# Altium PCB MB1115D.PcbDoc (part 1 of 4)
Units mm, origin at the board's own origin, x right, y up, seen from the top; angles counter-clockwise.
Board outline 66 x 97 mm, 2 copper layers (TOP, Bottom), stack 1.535 mm thick; 198 components, 186 nets, 760 pads, 493 vias.
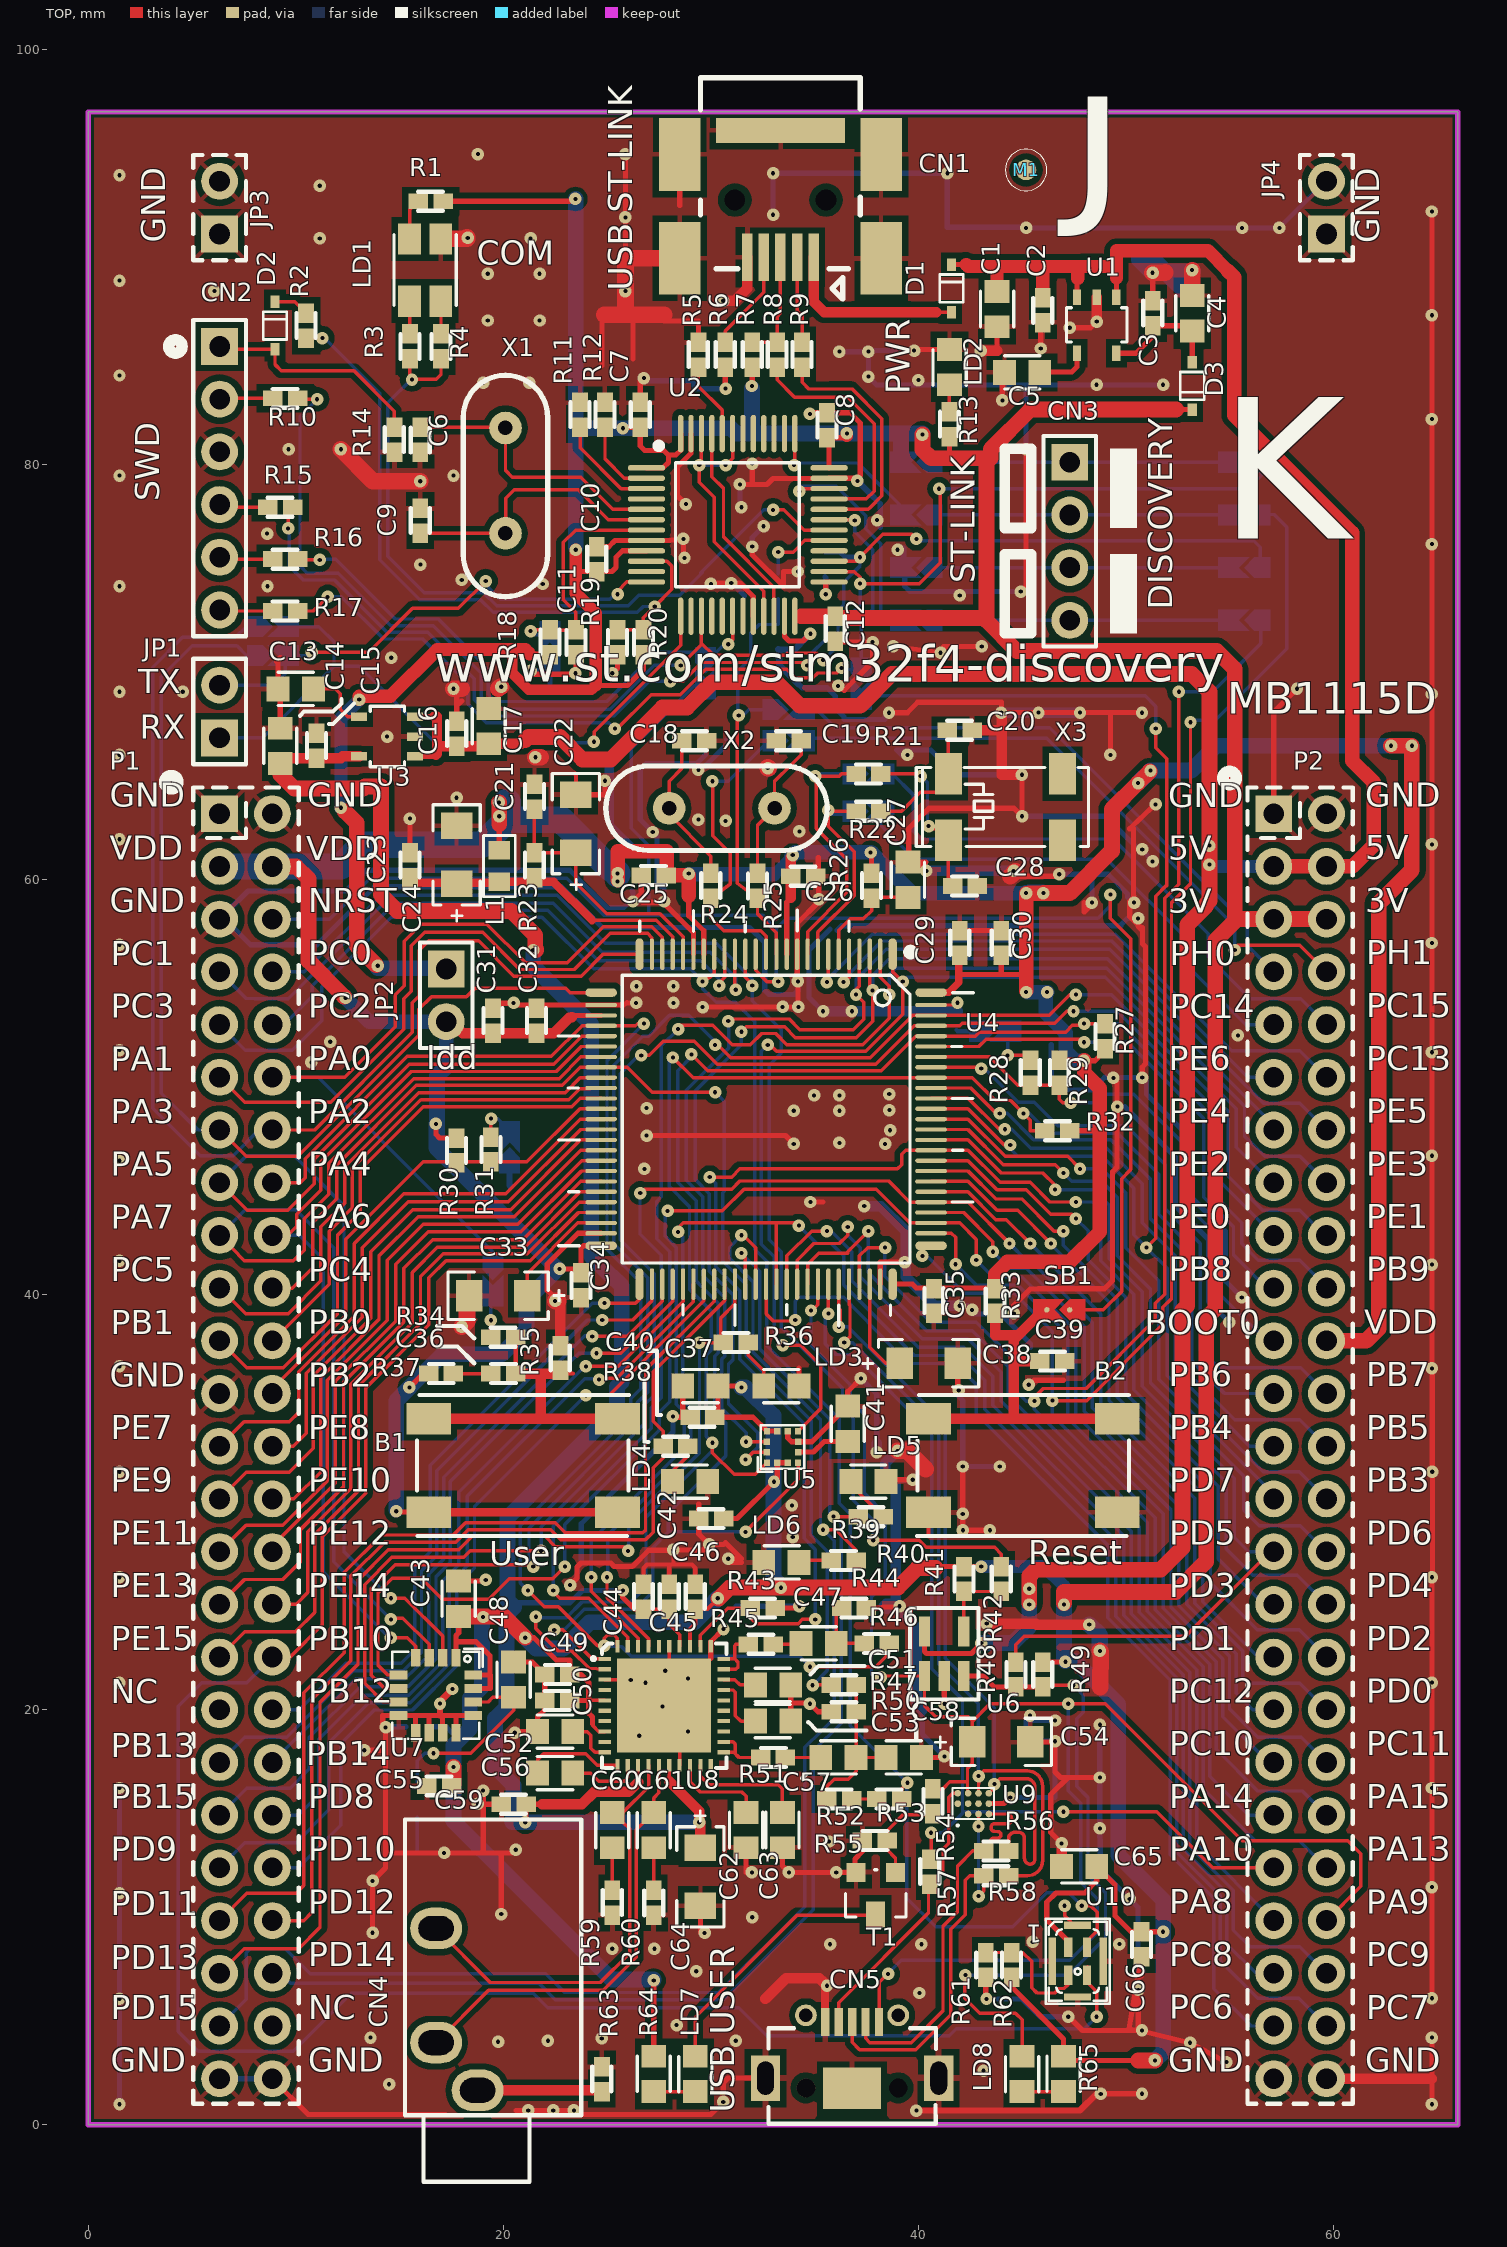
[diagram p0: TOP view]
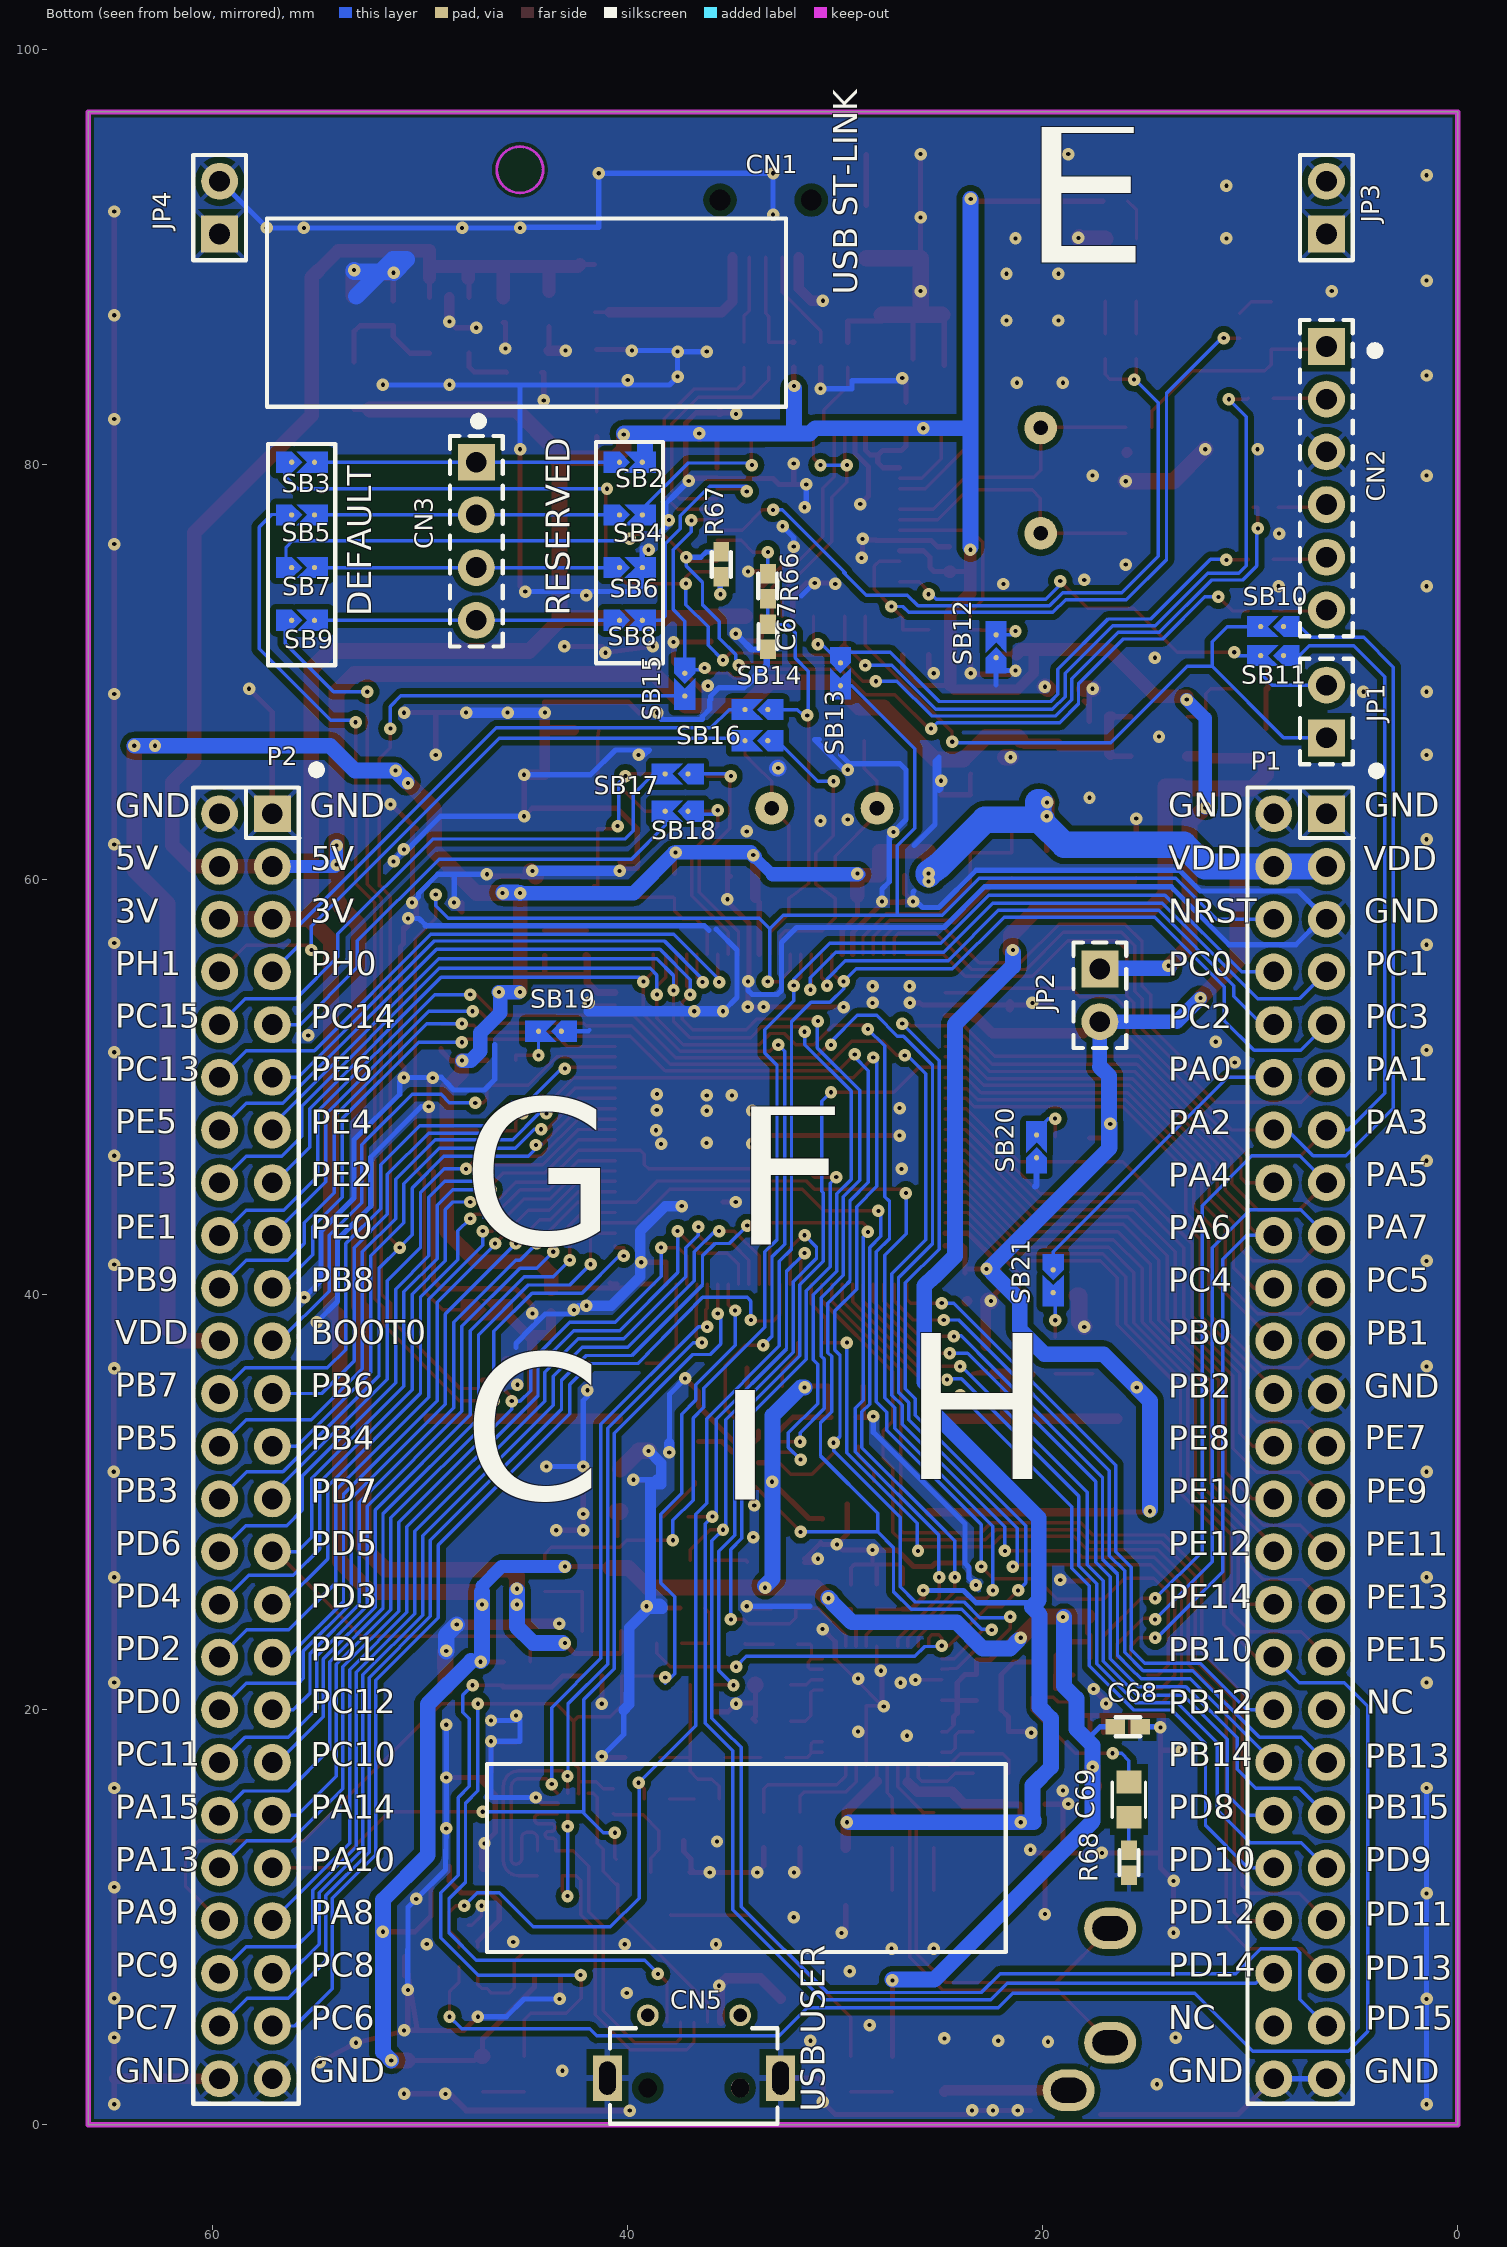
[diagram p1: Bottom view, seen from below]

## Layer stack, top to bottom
Top Mask: solder mask 0.018, Solder Resist, Dk 3.5
TOP: signal copper 0.035
Dielectric 1: dielectric 1.465, FR-4, Dk 4.8
Bottom: signal copper 0.035
Bottom Solder: solder mask 0.018, Solder Resist, Dk 3.5

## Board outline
0,0 66,0 66,97 0,97

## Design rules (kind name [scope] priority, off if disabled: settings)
Clearance Clearance_SB [(ObjectKind = 'Region')  and IsComponentPrimitive vs InNet('GND')     and InPolygon] p1: gap=0.28 ignorepadtopadclearanceinfootprint=TRUE
Clearance Clearance_JP2_SMD [HasFootprint('JP2_SMD (Primary)') and IsComponentPrimitive and IsRegion or IsTrack or InPolygon or IsVia vs HasFootprint('JP2_SMD (Primary)') and IsComponentPrimitive and IsRegion] p2: gap=0.1 ignorepadtopadclearanceinfootprint=FALSE
Clearance InPolygon_Template_1 [InNamedPolygon('Template_1') vs InNet('GND')] p3: gap=0.3 ignorepadtopadclearanceinfootprint=FALSE
Clearance InPolygon_Template_3 [InNamedPolygon('Template_3') vs InNet('GND')] p4: gap=0.3 ignorepadtopadclearanceinfootprint=FALSE
Clearance CopperToBoard [InPolygon vs IsKeepOut] p5: gap=0.15 ignorepadtopadclearanceinfootprint=FALSE
Clearance PadToCopper [IsPad vs InPolygon] p6: gap=0.3 ignorepadtopadclearanceinfootprint=FALSE
Clearance [All] p7: gap=0.15 ignorepadtopadclearanceinfootprint=FALSE except(0.28: Arc-Fill Arc-Poly Arc-Region Track-Fill Track-Poly Track-Region SMDPad-Fill SMDPad-Poly SMDPad-Region THPad-Fill THPad-Poly THPad-Region Via-Fill Via-Poly Via-Region)
ComponentClearance [All   and not HasFootprint('VIA') vs All and not HasFootprint('VIA')] p1: gap=0.07 collisioncheckmode=3 verticalgap=0.03 showdistances=FALSE
PolygonConnect PolygonConnect_HLGA [HasFootprint('HLGA-4.72-3.76-6LD (Primary)')] p1: connectstyle=Relief reliefconductorwidth=0.2 reliefentries=4 polygonreliefangle="45 Angle" airgapwidth=0.3
PolygonConnect PolygonConnect_CN5 [(ObjectKind = 'Pad') And ((Name = 'CN5-7') or  (Name = 'CN5-8'))] p2: connectstyle=Relief reliefconductorwidth=0.3 reliefentries=4 polygonreliefangle="90 Angle" airgapwidth=0.3
PolygonConnect PolygonConnect_Via [HasFootprint('VIA')] p3: connectstyle=Direct reliefconductorwidth=0.254 reliefentries=4 polygonreliefangle="90 Angle" airgapwidth=0.254
PolygonConnect [All] p4: thpad.connectstyle=Relief thpad.reliefconductorwidth=0.21 thpad.reliefentries=4 thpad.polygonreliefangle="45 Angle" thpad.airgapwidth=0.3 smdpad.connectstyle=Relief smdpad.reliefconductorwidth=0.23 smdpad.reliefentries=4 smdpad.polygonreliefangle="90 Angle" smdpad.airgapwidth=0.3 via.connectstyle=Direct via.reliefconductorwidth=0.2 via.reliefentries=4 via.polygonreliefangle="45 Angle" via.airgapwidth=0.2
RoutingVias [All] p1: holewidth=0.2 width=0.6 viastyle="Through Hole" minholewidth=0.2 minwidth=0.6 maxholewidth=0.2 maxwidth=0.6
SolderMaskExpansion [All] p1: expansion=0.05
Width [All] p1: maxlimit=1.27 minlimit=0.165 preferedwidth=0.175
29 further rules are at their usual default settings.

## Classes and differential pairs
component class U_MB1115_TOP: P1 P2
component class U_Audio: C44 C45 C46 C47 C49 C50 C51 C52 C53 C56 C57 C58 C59 C60 C61 C62 C63 C64 C65 C66 CN4 R43 R44 R45 R46 R47 R50 R51 R52 R53 R59 R60 R61 R62 R63 U8 U10
component class "U_IO Peripherals": B1 B2 C36 C37 C39 C40 C41 C42 C43 C48 C55 C68 C69 LD3 LD4 LD5 LD6 R33 R34 R35 R36 R37 R38 R39 R40 R68 SB1 SB21 U5 U7
component class U_ST_LINK: C1 C2 C3 C4 C5 C6 C7 C8 C9 C10 C11 C12 C13 C14 C15 C16 C17 C67 CN1 CN2 CN3 D1 D2 D3 JP1 JP2 JP3 JP4 LD1 LD2 R1 R2 R3 R4 R5 R6 R7 R8 R9 R10 R11 R12 R13 R14 R15 R16 R17 R18 R19 R20 R66 R67 SB2 SB3 SB4 SB5 SB6 SB7 SB8 SB9 SB10 SB11 SB12 SB13 SB15 U1 U2 U3 X1
component class U_STM32Fx: C18 C19 C20 C21 C22 C23 C24 C25 C26 C27 C28 C29 C30 C31 C32 C33 C34 C35 C38 L1 R21 R22 R23 R24 R25 R26 R27 R28 R29 R30 R31 R32 SB14 SB16 SB17 SB18 SB19 SB20 U4 X2 X3
component class U_USB_OTG_FS: C54 CN5 LD7 LD8 R41 R42 R48 R49 R54 R55 R56 R57 R58 R64 R65 T1 U6 U9

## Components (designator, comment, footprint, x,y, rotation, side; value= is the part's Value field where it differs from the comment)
B1 "SW-PUSH-CMS_BLUE" "BP1CMS (Primary)" 20.96,31.773 r90 top
B2 "SW-PUSH-CMS_BLACK" "BP1CMS (Primary)" 45.04,31.773 r270 top
C1 "1uF" "0603C (Primary)" 43.8,87.5 r90 top
C2 "100nF" "0402C (Primary)" 46,87.45 r180 top
C3 "100nF" "0402C (Primary)" 51.3,87.3 r0 top
C4 "1uF" "0603C (Primary)" 53.2,87.3 r90 top
C5 "10nF" "0603C (Primary)" 45,84.45 r0 top
C6 "20pF" "0402C (Primary)" 16,81.2 r180 top
C7 "100nF" "0402C (Primary)" 26.6,82.4 r0 top
C8 "100nF" "0402C (Primary)" 35.6,81.9 r0 top
C9 "20pF" "0402C (Primary)" 16,77.3 r0 top
C10 "100nF" "0402C (Primary)" 24.5,75.45 r0 top
C11 "100nF" "0402C (Primary)" 23.5,71.45 r180 top
C12 "100nF" "0402C (Primary)" 36,72.1 r0 top
C13 "10nF" "0603C (Primary)" 10,69.2 r0 top
C14 "1uF" "0603C (Primary)" 9.25,66.45 r90 top
C15 "100nF" "0402C (Primary)" 11,66.45 r0 top
C16 "100nF" "0402C (Primary)" 17.76,67.028 r0 top
C17 "1uF" "0603C (Primary)" 19.3,67.4 r270 top
C18 "20pF" "0402C (Primary)" 29.2,66.7 r270 top
C19 "20pF" "0402C (Primary)" 33.75,66.7 r90 top
C20 "6.8pF" "0402C (Primary)" 42,67.2 r90 top
C21 "100nF" "0402C (Primary)" 21.5,64 r0 top
C22 "1uF" "TAN-A (Primary)" 23.5,62.7 r270 top
C23 "100nF" "0402C (Primary)" 15.5,60.7 r0 top
C24 "1uF" "TAN-A (Primary)" 17.75,61.2 r270 top
C25 "100nF" "0402C (Primary)" 27.25,60.2 r90 top
C26 "100nF" "0402C (Primary)" 34.461,60.17 r90 top
C27 "1uF" "0603C (Primary)" 39.5,60 r90 top
C28 "6.8pF" "0402C (Primary)" 42.25,59.7 r90 top
C29 "100nF" "0402C (Primary)" 42,56.95 r0 top
C30 "100nF" "0402C (Primary)" 44,56.95 r0 top
C31 "100nF" "0402C (Primary)" 19.5,53.2 r0 top
C32 "100nF" "0402C (Primary)" 21.6,53.2 r0 top
C33 "2.2uF" "TAN-A (Primary)" 19.75,39.95 r0 top
C34 "100nF" "0402C (Primary)" 23.75,40.45 r180 top
C35 "100nF" "0402C (Primary)" 40.75,39.7 r0 top
C36 "[NA]" "0402C (Primary)" 20,36.2 r270 top
C37 "10uF" "0603C (Primary)" 29.5,35.6 r0 top
C38 "2.2uF" "TAN-A (Primary)" 40.5,36.7 r180 top
C39 "100nF" "0402C (Primary)" 46.45,36.8 r270 top
C40 "100nF" "0402C (Primary)" 29.6,34.1 r90 top
C41 "220nF" "0603C (Primary)" 36.598,33.782 r270 top
C42 "100nF" "0402C (Primary)" 30.02,29.21 r90 top
C43 "10uF" "0603C (Primary)" 17.85,25.35 r270 top
C44 "100nF" "0402C (Primary)" 26.75,25.45 r0 top
C45 "100nF" "0402C (Primary)" 28,25.45 r0 top
C46 "100nF" "0402C (Primary)" 29.25,25.45 r0 top
C47 "1uF" "0603C (Primary)" 35.2,23.2 r0 top
C48 "10nF" "0603C (Primary)" 20.5,21.45 r270 top
C49 "100nF" "0402C (Primary)" 22.6,21.7 r270 top
C50 "100nF" "0402C (Primary)" 22.6,20.45 r90 top
C51 "150pF" "0603C (Primary)" 33,21.2 r180 top
C52 "1uF" "0603C (Primary)" 22.5,18.95 r180 top
C53 "150pF" "0603C (Primary)" 33,19.45 r180 top
C54 "4.7uF" "TAN-A (Primary)" 44,18.45 r180 top
C55 "100nF" "0402C (Primary)" 16.916,16.332 r90 top
C56 "1uF" "0603C (Primary)" 22.5,16.95 r180 top
C57 "1uF" "0603C (Primary)" 36.15,17.7 r0 top
C58 "10nF" "0603C (Primary)" 39.3,17.7 r0 top
C59 "100nF" "0402C (Primary)" 20.5,15.45 r90 top
C60 "22nF" "0603C (Primary)" 25.25,14.2 r270 top
C61 "22nF" "0603C (Primary)" 27.25,14.2 r270 top
C62 "1uF" "0603C (Primary)" 31.7,14.2 r90 top
C63 "1uF" "0603C (Primary)" 33.45,14.2 r90 top
C64 "1uF" "TAN-A (Primary)" 29.5,11.95 r90 top
C65 "1uF" "0603C (Primary)" 47.75,12.45 r0 top
C66 "100nF" "0402C (Primary)" 50.75,8.7 r180 top
C67 "20pF" "0402C (Primary)" 33.25,71.7 r180 bottom
C68 "100nF" "0402C (Primary)" 15.91,19.177 r270 bottom
C69 "Capacitor" "0603C (Primary)" 15.85,15.672 r270 bottom value=470nF
CN1 "USB-MINI-typeB" "USB-MINI-B-SMD (Primary)" 33.359,92.751 r0 top
CN2 "Header 6" "HDR1X6 (PRIMARY)" 6.33,85.7 r270 top
CN3 "Header 4" "HEADER 4 (PRIMARY)" 47.299,80.121 r270 top
CN4 "ST-225-02" "JACK-ST-225 (Primary)" 17.76,5.56 r90 top
CN5 "USB-MICRO-AB" "USB-MICRO-AB (PRIMARY)" 36.81,4.95 r90 top
D1 "BAT60JFILM" "SOD323/A (Primary)" 41.6,88.5 r270 top
D2 "BAT60JFILM" "SOD323/A (Primary)" 9,86.7 r270 top
D3 "BAT60JFILM" "SOD323/A (Primary)" 53.2,83.8 r90 top
JP1 "JP2" "SIP2/2.54 (PRIMARY)" 6.33,66.837 r90 top
JP2 "" "SIP2/2.54 (PRIMARY)" 17.25,55.7 r270 top
JP3 "" "SIP2/2.54 (PRIMARY)" 6.33,91.12 r90 bottom
JP4 "" "SIP2/2.54 (PRIMARY)" 59.67,91.12 r90 bottom
L1 "Ferrite" "0603L (Primary)" 19.807,60.66 r270 top value=100uH
LD1 "LD_BICOLOR_CMS" "HSMF-A201 (Primary)" 16.236,89.38 r270 top
LD2 "LED, red" "0603D (Primary)" 41.5,84.7 r90 top
LD3 "LED, orange" "0603D (Primary)" 33.4,35.6 r0 top
LD4 "LED, green" "0603D (Primary)" 29,31 r0 top
LD5 "LED, red" "0603D (Primary)" 37.6,31 r0 top
LD6 "LED, blue" "0603D (Primary)" 33.4,27.1 r180 top
LD7 "LED, green" "0603D (Primary)" 29.25,2.45 r90 top
LD8 "LED, red" "0603D (Primary)" 45,2.45 r90 top
M1 "Comment" "SMDPAD-T (PRIMARY)" 45.192,94.206 r0 top
P1 "Header 25X2" "HDR2X25 (PRIMARY)" 7.6,32.7 r270 top
P2 "Header 25X2" "HDR2X25 (PRIMARY)" 58.4,32.7 r270 top
R1 "0" "0402R (Primary)" 16.5,92.7 r90 top
R2 "[NA]" "0402R (Primary)" 10.5,86.7 r0 top
R3 "100" "0402R (Primary)" 15.5,85.7 r180 top
R4 "100" "0402R (Primary)" 17,85.7 r180 top
R5 "100K" "0402R (Primary)" 29.4,85.3 r0 top
R6 "100K" "0402R (Primary)" 30.7,85.3 r0 top
R7 "1K5" "0402R (Primary)" 32,85.3 r0 top
R8 "0" "0402R (Primary)" 33.2,85.3 r0 top
R9 "0" "0402R (Primary)" 34.4,85.3 r0 top
R10 "22" "0402R (Primary)" 9.5,83.2 r90 top
R11 "[NA]" "0402R (Primary)" 23.7,82.4 r0 top
R12 "10K" "0402R (Primary)" 24.9,82.4 r0 top
R13 "1K" "0402R (Primary)" 41.5,81.95 r0 top
R14 "10K" "0402R (Primary)" 14.75,81.2 r0 top
R15 "22" "0402R (Primary)" 9.25,77.95 r90 top
R16 "22" "0402R (Primary)" 9.5,75.45 r90 top
R17 "22" "0402R (Primary)" 9.5,72.95 r90 top
R18 "100K" "0402R (Primary)" 22.25,71.45 r0 top
R19 "4K7" "0402R (Primary)" 25.5,71.45 r180 top
R20 "4K7" "0402R (Primary)" 26.75,71.45 r180 top
R21 "0" "0402R (Primary)" 37.6,65.1 r90 top
R22 "0" "0402R (Primary)" 37.6,63.3 r90 top
R23 "47" "0402R (Primary)" 21.5,60.7 r0 top value=1K
R24 "220" "0402R (Primary)" 30,59.7 r0 top
R25 "0" "0402R (Primary)" 32.25,59.7 r180 top
R26 "0" "0402R (Primary)" 37.75,59.7 r0 top
R27 "4.7K" "0402R (Primary)" 49,52.45 r180 top value=10K
R28 "510" "0402R (Primary)" 45.4,50.7 r0 top
R29 "[NA]" "0402R (Primary)" 46.8,50.7 r0 top
R30 "10K" "0402R (Primary)" 17.75,46.95 r0 top
R31 "510" "0402R (Primary)" 19.4,47 r180 top
R32 "4.7K" "0402R (Primary)" 46.7,47.9 r270 top value=10K
R33 "[NA]" "0402R (Primary)" 43.7,39.7 r180 top
R34 "330" "0402R (Primary)" 20,37.95 r90 top
R35 "220K" "0402R (Primary)" 22.75,36.95 r0 top value=10K
R36 "1K" "0402R (Primary)" 31.2,37.7 r270 top
R37 "100" "0402R (Primary)" 17,36.2 r270 top value=330
R38 "330" "0402R (Primary)" 28.3,32.7 r270 top value=1K
R39 "1K" "0402R (Primary)" 37.7,29.3 r270 top
R40 "510" "0402R (Primary)" 36.4,27.2 r90 top value=1K
R41 "10K" "0402R (Primary)" 42.2,26.3 r0 top value=1K
R42 "0" "0402R (Primary)" 44,26.3 r0 top
R43 "10K" "0402R (Primary)" 32.5,24.9 r90 top value=1K
R44 "100K" "0402R (Primary)" 36.9,24.9 r90 top value=1K
R45 "100" "0402R (Primary)" 32.4,23.15 r270 top value=1K
R46 "[NA]" "0402R (Primary)" 38,23.2 r90 top
R47 "[NA]" "0402R (Primary)" 36.4,21.2 r270 top
R48 "0" "0402R (Primary)" 44.7,21.7 r180 top
R49 "47K" "0402R (Primary)" 46,21.7 r0 top value=1K
R50 "100K" "0402R (Primary)" 36.4,19.9 r270 top value=1K
R51 "100" "0402R (Primary)" 33,17.7 r270 top value=1K
R52 "1.2K" "0402R (Primary)" 36.2,15.7 r90 top
R53 "0" "0402R (Primary)" 38.6,15.7 r90 top
R54 "47K" "0402R (Primary)" 40.7,15.6 r180 top value=1K
R55 "[NA]" "0402R (Primary)" 37.9,13.7 r270 top
R56 "22" "0402R (Primary)" 43.75,13.2 r90 top value=1K
R57 "0" "0402R (Primary)" 40.55,12.2 r0 top
R58 "22" "0402R (Primary)" 43.75,12 r90 top value=1K
R59 "51" "0402R (Primary)" 25.25,10.7 r0 top value=1K
R60 "51" "0402R (Primary)" 27.25,10.7 r180 top value=1K
R61 "0" "0402R (Primary)" 43.25,7.7 r180 top
R62 "[NA]" "0402R (Primary)" 44.5,7.7 r0 top
R63 "0" "0402R (Primary)" 24.75,2.2 r0 top
R64 "330" "0603R (Primary)" 27.25,2.45 r90 top value=1K
R65 "620" "0603R (Primary)" 47,2.45 r90 top value=1K
R66 "100" "0402R (Primary)" 33.25,74.15 r180 bottom
R67 "100" "0402R (Primary)" 35.5,75.2 r0 bottom
R68 "10K" "0402R (Primary)" 15.85,12.624 r180 bottom
SB1 "Circuit Breaker" "JP2_SMD (PRIMARY)" 46.793,39.271 r180 top
SB2 "Circuit Breaker" "JP2_SMD (PRIMARY)" 39.899,80.121 r180 bottom
SB3 "Circuit Breaker" "JP2_SMD (PRIMARY)" 55.699,80.121 r180 bottom
SB4 "Circuit Breaker" "JP2_SMD (PRIMARY)" 39.899,77.581 r180 bottom
SB5 "Circuit Breaker" "JP2_SMD (PRIMARY)" 55.699,77.581 r180 bottom
SB6 "Circuit Breaker" "JP2_SMD (PRIMARY)" 39.899,75.041 r180 bottom
SB7 "Circuit Breaker" "JP2_SMD (PRIMARY)" 55.699,75.041 r180 bottom
SB8 "Circuit Breaker" "JP2_SMD (PRIMARY)" 39.899,72.501 r180 bottom
SB9 "Circuit Breaker" "JP2_SMD (PRIMARY)" 55.699,72.501 r180 bottom
SB10 "Circuit Breaker" "JP2_SMD (PRIMARY)" 8.9,72.2 r0 bottom
SB11 "Circuit Breaker" "JP2_SMD (PRIMARY)" 8.9,70.8 r0 bottom
SB12 "Circuit Breaker" "JP2_SMD (PRIMARY)" 22.25,71.2 r90 bottom
SB13 "Circuit Breaker" "JP2_SMD (PRIMARY)" 29.75,69.95 r270 bottom
SB14 "Circuit Breaker" "JP2_SMD (PRIMARY)" 33.75,68.2 r0 bottom
SB15 "Circuit Breaker" "JP2_SMD (PRIMARY)" 37.25,69.45 r270 bottom
SB16 "Circuit Breaker" "JP2_SMD (PRIMARY)" 33.75,66.7 r0 bottom
SB17 "Circuit Breaker" "JP2_SMD (PRIMARY)" 37.6,65.1 r0 bottom
SB18 "Circuit Breaker" "JP2_SMD (PRIMARY)" 37.6,63.3 r0 bottom
SB19 "Circuit Breaker" "JP2_SMD (PRIMARY)" 43.7,52.7 r0 bottom
SB20 "Circuit Breaker" "JP2_SMD (PRIMARY)" 20.3,47.1 r90 bottom
SB21 "Circuit Breaker" "JP2_SMD (PRIMARY)" 19.5,40.7 r270 bottom
T1 "9013-SOT23" "SOT23 (Primary)" 37.95,11.15 r90 top
U1 "LD3985M33R" "SOT-23-5L (Primary)" 48.599,86.721 r270 top
U2 "STM32F103C8T6" "LQFP48 (Primary)" 31.3,77.1 r0 top
U3 "LD3985M25R" "SOT-23-5L (Primary)" 14.4,66.9 r180 top
U4 "STM32F411VET6U" "TQFP100_14X14 (PRIMARY)" 32.664,48.462 r180 top
U5 "LSM303AGR" ICC_LGA12_2X2_P050 33.456,32.664 r90 top
U6 "STMPS2141STR" "SOT23-5L (PRIMARY)" 41.25,22.7 r0 top
U7 "I3G4250D" ICC_LGA16_4X4_P065_H1P1 16.75,20.7 r270 top
U8 "CS43L22" "QFN40_6X6 (PRIMARY)" 27.75,20.2 r0 top
U9 "EMIF02-USB03F2" "FLIP CHIP (PRIMARY)" 42.9,15.475 r90 top
U10 "IMP34DT05TR" MIC_HCLGA_3X4X1_4LD 47.683,7.886 r180 top
X1 "8MHz" "XTAL1 (Primary)" 20.1,76.7 r90 top
X2 "8MHz" "XTAL1 (Primary)" 28,63.45 r0 top
X3 "XTAL_32K_20PPM" "MC306-CRYSTAL (Primary)" 44.2,63.5 r0 top

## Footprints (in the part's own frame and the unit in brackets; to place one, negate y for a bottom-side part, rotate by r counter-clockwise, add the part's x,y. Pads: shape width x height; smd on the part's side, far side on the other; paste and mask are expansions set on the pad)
"0402C (Primary)" [mil]
  rect 30x37 smd paste+0 mask+1.97: 1(0,23.62) 2(0,-23.62)
  silkscreen extent -18,-23 18,24
"0402R (Primary)" [mil]
  rect 30x37 smd paste+0 mask+1.97: 1(0,23.62) 2(0,-23.62)
  silkscreen extent -18,-23 18,24
"0603C (Primary)" [mm]
  rect 1.1x1.2 smd paste+0 mask+0.05: 1(-0.85,0) 2(0.85,0)
  silkscreen extent -0.85,-0.8 0.86,0.8
"0603D (Primary)" [mm]
  rect 1.1x1.2 smd paste+0 mask+0.05: 1(-0.85,0) 2(0.85,0)
  silkscreen extent -0.86,-0.8 0.84,0.8
"0603L (Primary)" [mil]
  rect 35x40 smd paste+0 mask+1.97: 1(-30,0) 2(30,0)
  silkscreen extent -58,-30 58,30
"0603R (Primary)" [mm]
  rect 1.1x1.2 smd paste+0 mask+0.05: 1(-0.85,0) 2(0.85,0)
  silkscreen extent -0.85,-0.8 0.86,0.8
"BP1CMS (Primary)" [mm]
  rect 1.52x2.16 smd paste+0 mask+0.05: 1(-2.25,-4.55) 2(2.25,-4.55) 3(2.25,4.55) 4(-2.25,4.55)
  silkscreen extent -3.4,-5.1 3.4,5.12
"FLIP CHIP (PRIMARY)" [mm]
  round 0.32 smd paste-0.05 mask+0.05: A2(0,1) A3(0.5,1) B1(-0.5,0.5) B2(0,0.5) B3(0.5,0.5) C1(-0.5,0) C2(0,0) C3(0.5,0) D1(-0.5,-0.5) D2(0,-0.5) D3(0.5,-0.5)
  silkscreen extent -1.1,-0.75 0.75,1.25
"HDR1X6 (PRIMARY)" [mil]
  rect 70x70 / inner round 60 / far side rect 70x70 hole 39.37 paste+0 mask+1.97: 1(0,0)
  round 70 / inner round 60 / far side round 70 hole 39.37 paste+0 mask+1.97: 2(100,0) 3(200,0) 4(300,0) 5(400,0) 6(500,0)
  silkscreen extent -50,-50 550,50
"HDR2X25 (PRIMARY)" [mil]
  rect 70x70 / inner round 60 / far side rect 70x70 hole 39.37 paste+0 mask+1.97: 1(-1200,-50)
  round 70 / inner round 60 / far side round 70 hole 39.37 paste+0 mask+1.97: 2(-1200,50) 3(-1100,-50) 4(-1100,50) 5(-1000,-50) 6(-1000,50) 7(-900,-50) 8(-900,50) 9(-800,-50) 10(-800,50) 11(-700,-50) 12(-700,50) 13(-600,-50) 14(-600,50) 15(-500,-50) 16(-500,50) 17(-400,-50) 18(-400,50) 19(-300,-50) 20(-300,50) 21(-200,-50) 22(-200,50) 23(-100,-50) 24(-100,50) 25(0,-50) 26(0,50) 27(100,-50) 28(100,50) 29(200,-50) 30(200,50) 31(300,-50) 32(300,50) 33(400,-50) 34(400,50) 35(500,-50) 36(500,50) 37(600,-50) 38(600,50) 39(700,-50) 40(700,50) 41(800,-50) 42(800,50) 43(900,-50) 44(900,50) 45(1000,-50) 46(1000,50) 47(1100,-50) 48(1100,50) 49(1200,-50) 50(1200,50)
  silkscreen extent -1250,-100 1248,100
"HEADER 4 (PRIMARY)" [mil]
  rect 70x70 / inner round 60 / far side rect 70x70 hole 39.37 paste+0 mask+1.97: 1(0,0)
  round 70 / inner round 60 / far side round 70 hole 39.37 paste+0 mask+1.97: 2(100,0) 3(200,0) 4(300,0)
  silkscreen extent -50,-50 350,50
"HSMF-A201 (Primary)" [mm]
  rect 1.5x1.1 smd paste+0 mask+0.05: 1(-1.5,0.75) 2(1.5,0.75) 3(1.5,-0.75) 4(-1.5,-0.75)
  silkscreen extent -1.7,-1.5 1.7,1.5
ICC_LGA12_2X2_P050 [mm] "MCD-00709"
  rect 0.325x0.3 smd mask+0.05: 1(-0.763,0.75) 2(-0.763,0.25) 3(-0.763,-0.25) 4(-0.763,-0.75) 7(0.763,-0.75) 8(0.763,-0.25) 9(0.763,0.25) 10(0.763,0.75)
  rect 0.3x0.325 smd mask+0.05: 5(-0.25,-0.762) 6(0.25,-0.762) 11(0.25,0.763) 12(-0.25,0.763)
  silkscreen extent -1.2,-1.05 1.05,1.2, body extent -1.05,-1.05 1.05,1.05, height 1.01
ICC_LGA16_4X4_P065_H1P1 [mm] "MCD-01963"
  rect 0.85x0.45 smd mask+0.05: 1(-1.8,0.975) 2(-1.8,0.325) 3(-1.8,-0.325) 4(-1.8,-0.975) 9(1.8,-0.975) 10(1.8,-0.325) 11(1.8,0.325) 12(1.8,0.975)
  rect 0.45x0.85 smd mask+0.05: 5(-0.975,-1.8) 6(-0.325,-1.8) 7(0.325,-1.8) 8(0.975,-1.8) 13(0.975,1.8) 14(0.325,1.8) 15(-0.325,1.8) 16(-0.975,1.8)
  silkscreen extent -2.25,-2.1 2.1,2.25, body extent -2.1,-2.1 2.1,2.1, height 1.1
"JACK-ST-225 (Primary)" [mm]
  oval 2x2.5 / inner round 1.524 / far side oval 2x2.5 hole 1.2 slot 1.7 at 90 deg paste+0 mask+0.05: 1(-3.9,-1) 2(-1.6,1) 3(3.9,1)
  silkscreen extent -8.31,-6 9.15,2.5
"JP2_SMD (PRIMARY)" [mil]
  round 10 smd paste-3.94: 1(-19.68,0) 2(23.62,0)
  TOP region: -19.68,19.68 -49.21,19.68 -49.21,-19.69 -19.68,-19.69 0,0
  TOP region: -9.84,-19.69 49.21,-19.69 49.21,19.68 -9.84,19.68 9.84,0
  TOP pour cut-out: -49.21,19.68 49.21,19.68 49.21,-19.69 -49.21,-19.69
"LQFP48 (Primary)" [mm]
  oval 1.803x0.257 smd paste+0 mask+0.05: 1(-4.4,2.75) 12(-4.4,-2.75) 25(4.4,-2.75) 36(4.4,2.75)
  oval 1.803x0.254 smd paste+0 mask+0.05: 2(-4.4,2.25) 3(-4.4,1.75) 4(-4.4,1.25) 5(-4.4,0.75) 6(-4.4,0.25) 7(-4.4,-0.25) 8(-4.4,-0.75) 9(-4.4,-1.25) 10(-4.4,-1.75) 11(-4.4,-2.25) 26(4.4,-2.25) 27(4.4,-1.75) 28(4.4,-1.25) 29(4.4,-0.75) 30(4.4,-0.25) 31(4.4,0.25) 32(4.4,0.75) 33(4.4,1.25) 34(4.4,1.75) 35(4.4,2.25)
  oval 0.257x1.803 smd paste+0 mask+0.05: 13(-2.75,-4.4) 24(2.75,-4.4) 37(2.75,4.4) 48(-2.75,4.4)
  oval 0.254x1.803 smd paste+0 mask+0.05: 14(-2.25,-4.4) 15(-1.75,-4.4) 16(-1.25,-4.4) 17(-0.75,-4.4) 18(-0.25,-4.4) 19(0.25,-4.4) 20(0.75,-4.4) 21(1.25,-4.4) 22(1.75,-4.4) 23(2.25,-4.4) 38(2.25,4.4) 39(1.75,4.4) 40(1.25,4.4) 41(0.75,4.4) 42(0.25,4.4) 43(-0.25,4.4) 44(-0.75,4.4) 45(-1.25,4.4) 46(-1.75,4.4) 47(-2.25,4.4)
  silkscreen extent -3.96,-2.98 2.97,3.96
"MC306-CRYSTAL (Primary)" [mm]
  rect 1.3x2 smd paste+0 mask+0.05: 1(-2.75,-1.6) 2(2.75,-1.6) 3(2.75,1.6) 4(-2.75,1.6)
  silkscreen extent -4.3,-1.9 4,1.9
MIC_HCLGA_3X4X1_4LD [mm]
  rect 0.4x0.95 smd paste+0 mask+0.05: 1(0.45,-0.675) 2(0.45,0.675) 3(-0.45,0.675) 4(-0.45,-0.675)
  rect 1.3x0.35 smd paste+0 mask+0.05: 5(0,-1.725) 6(0,1.725)
  rect 0.35x2.3 smd paste+0 mask+0.05: 7(1.225,0) 8(-1.225,0)
  silkscreen extent -1.55,-2.05 1.55,2.05, body extent -1.45,-1.95 1.45,1.95, height 1.03
"QFN40_6X6 (PRIMARY)" [mm]
  rect 4.1x4.1 on Top Solder paste+0 mask+0: 0(0,0)
  rect 3.9x3.9 on Top Paste paste+0 mask+0: 0(0,0)
  rect 0.6x0.2 smd paste-0.05 mask+0.05: 1(-2.87,2.25) 2(-2.87,1.75) 3(-2.87,1.25) 4(-2.87,0.75) 5(-2.87,0.25) 6(-2.87,-0.25) 7(-2.87,-0.75) 8(-2.87,-1.25) 9(-2.87,-1.75) 10(-2.87,-2.25) 21(2.87,-2.25) 22(2.87,-1.75) 23(2.87,-1.25) 24(2.87,-0.75) 25(2.87,-0.25) 26(2.87,0.25) 27(2.87,0.75) 28(2.87,1.25) 29(2.87,1.75) 30(2.87,2.25)
  rect 0.2x0.6 smd paste-0.05 mask+0.05: 11(-2.25,-2.87) 12(-1.75,-2.87) 13(-1.25,-2.87) 14(-0.75,-2.87) 15(-0.25,-2.87) 16(0.25,-2.87) 17(0.75,-2.87) 18(1.25,-2.87) 19(1.75,-2.87) 20(2.25,-2.87) 31(2.25,2.87) 32(1.75,2.87) 33(1.25,2.87) 34(0.75,2.87) 35(0.25,2.87) 36(-0.25,2.87) 37(-0.75,2.87) 38(-1.25,2.87) 39(-1.75,2.87) 40(-2.25,2.87)
  rect 4.53x4.53 smd paste-10 mask-10: 41(0,0)
  silkscreen extent -3.48,-3 3,3
"SIP2/2.54 (PRIMARY)" [mil]
  rect 70x70 / inner round 60 / far side rect 70x70 hole 39.37 paste+0 mask+1.97: 1(0,0)
  round 70 / inner round 60 / far side round 70 hole 39.37 paste+0 mask+1.97: 2(100,0)
  silkscreen extent -50,-50 150,50
"SMDPAD-T (PRIMARY)" [mil]
  round 39 smd paste-39 mask+1.97: 1(0,0)
  Bottom keep-out lines w5.32: -43.82,0.3 ccw(c0.2,0.3) 44.22,0.3 ccw(c0.2,0.3) -43.82,0.3
  silkscreen extent -39,-39 39,39
"SOD323/A (Primary)" [mm]
  rect 0.6x0.45 smd paste+0 mask+0.05: 1(1.143,0) 2(-1.143,0)
  silkscreen extent -0.67,-0.57 0.67,0.57
"SOT23 (Primary)" [mil]
  rect 36x36 smd paste+0 mask+1.97: 1(40,-37.5) 2(40,37.5)
  rect 50x36 smd paste+0 mask+1.97: 3(-40,0.5)
  silkscreen extent -45,-58 45,58
"SOT23-5L (PRIMARY)" [mm]
  rect 0.55x1.45 smd paste-0.05 mask+0.05: 1(-0.95,-1.075) 2(0,-1.075) 3(0.95,-1.075) 4(0.95,1.075) 5(-0.95,1.075)
  silkscreen extent -1.65,-2.2 1.65,2.2
"SOT-23-5L (Primary)" [mil]
  rect 30x16 smd paste+0 mask+1.97: 1(-53.15,37.4) 2(-53.15,0) 3(-53.15,-37.4) 4(53.15,-37.4) 5(53.15,37.4)
  silkscreen extent -33,-58 32,57
"TAN-A (Primary)" [mil]
  rect 50x60 smd paste+0 mask+1.97: 1(55,0) 2(-55,0)
  silkscreen extent -95,-45 126,45
"TQFP100_14X14 (PRIMARY)" [mil]
  oval 16x60 smd paste-1.97 mask+1.97: 1(-240.16,-312.99) 25(240.16,-312.99) 51(240.16,312.99) 75(-240.16,312.99)
  oval 8x60 smd paste-1.97 mask+1.97: 2(-216.54,-312.99) 3(-196.85,-312.99) 4(-177.17,-312.99) 5(-157.48,-312.99) 6(-137.8,-312.99) 7(-118.11,-312.99) 8(-98.43,-312.99) 9(-78.74,-312.99) 10(-59.06,-312.99) 11(-39.37,-312.99) 12(-19.68,-312.99) 13(0,-312.99) 14(19.69,-312.99) 15(39.37,-312.99) 16(59.06,-312.99) 17(78.74,-312.99) 18(98.43,-312.99) 19(118.11,-312.99) 20(137.8,-312.99) 21(157.48,-312.99) 22(177.17,-312.99) 23(196.85,-312.99) 24(216.54,-312.99) 52(216.54,312.99) 53(196.85,312.99) 54(177.17,312.99) 55(157.48,312.99) 56(137.8,312.99) 57(118.11,312.99) 58(98.43,312.99) 59(78.74,312.99) 60(59.06,312.99) 61(39.37,312.99) 62(19.69,312.99) 63(0,312.99) 64(-19.68,312.99) 65(-39.37,312.99) 66(-59.06,312.99) 67(-78.74,312.99) 68(-98.43,312.99) 69(-118.11,312.99) 70(-137.8,312.99) 71(-157.48,312.99) 72(-177.17,312.99) 73(-196.85,312.99) 74(-216.54,312.99)
  oval 60x16 smd paste-1.97 mask+1.97: 26(312.99,-240.16) 50(312.99,240.16) 76(-312.99,240.16) 100(-312.99,-240.16)
  oval 60x8 smd paste-1.97 mask+1.97: 27(312.99,-216.54) 28(312.99,-196.85) 29(312.99,-177.17) 30(312.99,-157.48) 31(312.99,-137.8) 32(312.99,-118.11) 33(312.99,-98.43) 34(312.99,-78.74) 35(312.99,-59.06) 36(312.99,-39.37) 37(312.99,-19.68) 38(312.99,0) 39(312.99,19.69) 40(312.99,39.37) 41(312.99,59.06) 42(312.99,78.74) 43(312.99,98.43) 44(312.99,118.11) 45(312.99,137.8) 46(312.99,157.48) 47(312.99,177.17) 48(312.99,196.85) 49(312.99,216.54) 77(-312.99,216.54) 78(-312.99,196.85) 79(-312.99,177.17) 80(-312.99,157.48) 81(-312.99,137.8) 82(-312.99,118.11) 83(-312.99,98.43) 84(-312.99,78.74) 85(-312.99,59.06) 86(-312.99,39.37) 87(-312.99,19.69) 88(-312.99,0) 89(-312.99,-19.68) 90(-312.99,-39.37) 91(-312.99,-59.06) 92(-312.99,-78.74) 93(-312.99,-98.43) 94(-312.99,-118.11) 95(-312.99,-137.8) 96(-312.99,-157.48) 97(-312.99,-177.17) 98(-312.99,-196.85) 99(-312.99,-216.54)
  silkscreen extent -393,-396 394,392
"USB-MICRO-AB (PRIMARY)" [mm]
  rect 1.35x0.4 smd paste-0.05 mask+0.05: 1(0,-1.3) 2(0,-0.65) 3(0,0) 4(0,0.65) 5(0,1.3)
  rect 2x2.8 smd paste-0.05 mask+0.05: 6(-3.2,0)
  rect 2.2x1.4 / inner round 1.524 / far side rect 2.2x1.4 hole 0.8 slot 1.6 at 0 deg paste+0 mask+0.05: 7(-2.7,4.175) 8(-2.7,-4.175)
  round 0.9 / inner round 1.524 / far side round 0.9 hole 0.9 unplated paste+0 mask+0.2: 9(-3.175,2.225)
  round 0.8 / inner round 1.524 / far side round 0.8 hole 0.9 unplated paste+0 mask+0.3: 10(-3.175,-2.225)
  round 1.05 / inner round 1.524 / far side round 1.05 hole 0.65 paste+0 mask+0.05: 11(0.325,2.225) 12(0.325,-2.225)
  silkscreen extent -4.9,-4.04 -0.3,4.03
"USB-MINI-B-SMD (Primary)" [mm]
  rect 0.508x2.3 smd paste+0 mask+0.05: 1(1.597,-2.75) 2(0.797,-2.75) 3(-0.003,-2.75) 4(-0.803,-2.75) 5(-1.603,-2.75)
  rect 2x3.5 smd paste+0 mask+0.05: 6(-4.853,-2.8) 7(-4.853,2.2) 8(4.847,-2.8) 9(4.847,2.2)
  rect 6.2x1.2 smd paste+0 mask+0.05: 10(0,3.35)
  round 0.9 / inner round 1.524 / far side round 0.9 hole 1 unplated paste+0 mask+0.2: 11(2.194,0) 12(-2.2,0)
  silkscreen extent -3.85,-4.76 3.85,5.9
"XTAL1 (Primary)" [mm]
  round 1.575 / inner round 1.524 / far side round 1.575 hole 0.7 paste+0 mask+0.05: 1(-0.009,-0.005) 2(5.071,-0.005)
  silkscreen extent -3.06,-2.04 7.61,2.03

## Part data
B1: "Non-Open Push-Button 0.1A 24V", Manuf_1=wealthmetal, Manuf_2=FARNELL, Manuf_Part_1=TD0341X-G01-BLU, Manuf_Part_2=535-930
B2: "Non-Open Push-Button 0.1A 24V", Manuf_1=wealthmetal, Manuf_2=FARNELL, Manuf_Part_1=TD0341X-G01-BLA, Manuf_Part_2=535-930
C1 C4 C14 C17 C27 C47 C52 C56 C57 C62 C63 C65: library part Cap_1uF_X5R_10%_0603, "Capacitor,1uF,16V,X5R,10%,0603,YAGEO", Manuf_1=YAGEO, Manuf_Part_1=CC0603KRX5R7BB105
C2 C3 C7 C8 C10 C11 C12 C15 C16 C21 C23 C25 C26 C29 C30 C31 C32 C34 C35 C39 C40 C42 C44 C45 C46 C49 C50 C55 C59 C66 C68: library part Cap_100nF_X7R_10%_0402, "Capacitor,100nF,16V,X7R,10%,0402,YAGEO", Manuf_1=YAGEO, Manuf_Part_1=CC0402KRX7R7BB104
C5 C13 C48 C58: library part Cap_10nF_X7R_10%_0603, "Capacitor,10nF,50V,X7R,10%,0603,YAGEO", Manuf_1=YAGEO, Manuf_Part_1=CC0603KRX7R9BB103
C6 C9 C18 C19 C67: library part Cap_20pF_NPO_5%_0402, "Capacitor,20pF,50V,NPO,5%,0402,YAGEO", Manuf_1=YAGEO, Manuf_Part_1=CC0402JRNPO9BN200
C20 C28: library part Cap_6.8pF_NPO_4%_0402, "Capacitor,6.8pF,50V,NPO,4%,0402,AVX", Manuf_1=AVX, Manuf_Part_1=04025A6R8CAT2A
C22 C24 C64: library part Cap_1uF_POL_10%_TANA, "Polarized Capacitor,1uF,16V,10%,typeA,AVX", Manuf_1=AVX, Manuf_Part_1=TAJA105K016R
C33 C38: library part Cap_2.2uF_X7R_10%_0805, "Capacitor,2.2uF,16V, X7R,10%,0805,YAGEO", Manuf_1=YAGEO, Manuf_Part_1=CC0805KKX7R7BB225
C36: library part Cap_NA_0402, "Capacitor,NA,0402"
C37 C43: library part Cap_10uF_X5R_10%_0603, "Capacitor,10uF,6.3V,X5R,20%,0603,YAGEO", Manuf_1=YAGEO, Manuf_Part_1=CC0603KRX5R5BB106
C41: library part Cap_220nF_X7R_10%_0603, "Capacitor,220nF,16V,X7R,10%,0603,YAGEO", Manuf_1=YAGEO, Manuf_Part_1=CC0603KRX7R7BB224
C51 C53: library part Cap_150pF_NPO_5%_0603, "Capacitor,150pF,50V,NPO,5%,0603,YAGEO", Manuf_1=YAGEO, Manuf_Part_1=CC0603JRNPO9BN151
C54: library part Cap_4.7uF_POL_10%_TANA, "Polarized Capacitor,4.7uF,16V,10%,typeA,AVX", Manuf_1=AVX, Manuf_Part_1=TAJA475K016R
C60 C61: library part Cap_22nF_X7R_10%_0603, "Capacitor,22nF,50V,X7R,10%,0603,YAGEO", Manuf_1=YAGEO, Manuf_Part_1=CC0603KRX7R9BB223
C69: library part MCD-01006, "Capacitor, MLCC, 470nF, 16V, X7R, 10%, 0603, T=0.8mm", Manufacturer=YAGEO, Manufacturer_Part_Number=CC0603KRX7R7BB474, Package=C0603
CN1: library part "USB-MINI-typeB connector", "USB-MINI-typeB connector", Manuf_2=lyconn, Manuf_Part_1=5075BMR-05-SM, Manuf_Part_2=218205M1110T
CN2: "Header, 6-Pin"
CN3: "Header, 4-Pin"
CN4: "Connector Jack 35mm", Manuf_1="XIEJIA Electronics"
CN5: "USB-MICRO-AB, 47590-0001, SMT, MOLEX", Manuf_1=MOLEX, Manuf_Part_1=47590-0001
D1 D2 D3: Manuf_1=STM
JP2 JP3 JP4: library part JP2
L1: library part BEAD_600R_350MA_0603, "Bead,600R,350mA,0603,FCM1608KF-601T03,Tai-tech", Manuf_1=Tai-tech, Manuf_2=TDK, Manuf_Part_1=FCM1608KF-601T03, Manuf_Part_2=MPZ1608S300A
LD1: "Bicolor Led", Manuf_1="Avago Technologies", Manuf_2=everluck, Manuf_Part_1=HSMF-A201-A00J1, Manuf_Part_2=LE-RGW35280
LD2 LD5 LD8: library part LED_red, "LED, red, 0603", Manuf_1=everlight, Manuf_Part_1=19-213-R6C-AP1Q2B/3T
LD3: library part LED_orange, "LED, orange, 0603", Manuf_1=everlight, Manuf_Part_1=19-217/S2C-AM2N2VY/3T
LD4 LD7: library part LED_green, "LED, green, 0603", Manuf_1=everlight, Manuf_Part_1=19-213SYGC/S530-E2/TR8
LD6: library part LED_blue, "LED, blue, 0603", Manuf_1=everlight, Manuf_Part_1=19-217/BHC-ZL1M2RY/3T
M1: library part SMDPAD-T
P1 P2: "Header, 25-Pin, Dual row"
R1 R8 R9 R21 R22 R25 R26 R42 R48 R53 R57 R61 R63: library part Res_0_0402, "Resistor,0,0402"
R2 R11 R29 R33 R46 R47 R55 R62: library part Res_NA_0402, "Resistor,[NA],0402"
R3 R4 R5 R6 R7 R10 R12 R13 R14 R15 R16 R17 R18 R19 R20 R27 R30 R31 R32 R34 R35 R37 R41 R43 R44 R45 R49 R50 R51 R52 R54 R59 R60 R64 R66 R67 R68: library part res1, "Resistor"
R23 R24 R28 R36 R38 R39 R40 R56 R58 R65: library part Res1, "Resistor"
T1: "NPN Bipolar Transistor", Manuf_1=unisonic, Manuf_Part_1=MMBT9013
U1 U3: "Ultra low drop-low noise BiCMOS voltage, regulators low ESR capacitors compatible", Manuf_1=STM
U2: "Medium-density performance line ARM-based 32-bit MCU with 64KB Flash", Manuf_1=STM
U4: library part STM32F401VCT6U, "STM32 Tiny Manta (STM32F401VCT6U)", Manuf_1=STM
U5: library part MCD-00709, "3D accelerometer and 3D magnetometer", Manufacturer=STMICROELECTRONICS
U6: "Enhanced single channel power switches", Manuf_1=STM
U7: library part MCD-01963, "MEMS motion sensor: 3-axis digital output gyroscope LG4-16 4x4mm", Alternate_Manufacturer=N/A, Manufacturer=STMICROELECTRONICS, Package=LGA-16
U8: "Low Power, Stereo DAC w/Headphone & Speaker Amps", Manuf_1=Cirrus, Manuf_Part_1=CS43L22-CNZ
U9: "2-line IPAD, EMI filter including ESD protection", Manuf_1=STM
U10: library part MCD-01715, "MEMS audio sensor omnidirectional digital microphone for industrial applications", Manufacturer=STMICROELECTRONICS, Package=HCLGA-4LD
X1 X2: library part XTAL_8MHZ_20PPM, "Crystal Oscillator,8Mhz,20PF,20PPM,-10-70 degree,DIP,HC-49S", Manuf_Part_1=HC-49S-C20QSA-8.000MHZ
X3: library part XTAL_32K, "Crystal oscillator for clock,32.768K,6PF,20PPM,-40~85 degree,SMT", Manuf_Part_1=ETMB32.768W060BMPF

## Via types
v1: diameter 0.6, hole 0.2, TOP to Bottom, tented both sides, 492 vias
v2: diameter 0.6, hole 0.2, TOP to Bottom, tented bottom, 1 vias

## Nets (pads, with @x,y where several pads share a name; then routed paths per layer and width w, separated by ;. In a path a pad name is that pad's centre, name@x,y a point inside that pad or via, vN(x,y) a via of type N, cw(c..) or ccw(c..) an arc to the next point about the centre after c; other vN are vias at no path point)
2V5: C14.1 C15.2 C44.2 C45.2 C59.2 C64.1 U3.5 U8.13 U8.16 U8.34 | length 102.4
  TOP w0.165: 26.5,16.51 U8.13@26.5,17.33 ; C44.2@26.75,24.85 C45.2@28,24.85 28,24.124 28.5,23.624 U8.34@28.5,23.07 ; 28,16.672 U8.16@28,17.33
  TOP w0.25: C14.1@9.25,65.6 C14.1@9.315,65.6 ; v1(21.062,14.577) 21.1,14.577 C59.2@21.1,15.45 21.888,15.45 ; v1(25.761,25.753) 25.748,25.753 25.748,25.423 26.321,24.85 C44.2@26.75,24.85 ; 28,16.558 28,16.672
  TOP w0.5: C14.1@9.315,65.6 9.565,65.85 C15.2@11,65.85 12.162,65.85 12.262,65.95 U3.5@13.05,65.95
  TOP w0.508: 21.888,15.45 23.789,15.45 24.377,16.037 26.028,16.037 26.5,16.51 ; 28,16.558 29.444,15.114 v1(29.444,14.577) 29.5,14.577 C64.1@29.5,13.347
  TOP w0.762: C14.1@9.25,65.6 9.25,65.073 9.924,64.399 13.252,64.399 13.34,64.488 14.102,64.488 14.102,59.281 14.89,58.494 20.376,58.494 21.545,57.325 21.545,56.677 21.57,56.652 v1@21.57,56.614
  Bottom w0.25: 20.325,25.156 23.221,25.156 23.818,25.753 v1(25.761,25.753)
  Bottom w0.762: v1@21.443,56.5 21.443,55.826 24.237,53.032 24.237,41.857 25.177,40.917 25.204,40.917 25.71,40.426 25.71,35.799 25.482,35.57 25.482,34.523 20.198,29.24 20.198,25.283 20.325,25.156 20.531,24.95 20.153,24.572 20.153,20.12 19.607,19.573 19.607,17.239 20.491,16.355 20.491,14.691 20.44,14.691 20.44,14.577 v1(21.062,14.577) v1@29.35,14.577
  other v1: 21.443,56.614
3V: C7.2 C8.2 C10.2 C12.1 C37.2 C40.2 C42.2 C43.2 C46.2 C49.1 C50.2 C55.2 C65.2 C66.2 C68.2 D3.2 JP2.1 P2.5 P2.6 R1.2 R7.2 R13.2 R18.2 R20.1 R41.1 R49.1 R62.2 R64.2 R65.2 SB2.2 U2.1 U2.9 U2.24 U2.36 U2.48 U5.2 U5.3 U5.9 U5.10 U7.1 U7.15 U7.16 U8.5 U8.8 U8.33 U10.1 | length 351.4
  TOP w0.165: 24.123,20.45 U8.5@24.88,20.45 ; 24.301,19.314 24.301,19.251 24.601,18.95 U8.8@24.88,18.95 ; U10.1@47.233,8.561 U10.1@47.233,8.831
  TOP w0.2: U8.33@29,23.07 29,23.89 29.25,24.14 ; C46.2@29.25,24.85 29.25,24.14 ; v1@30.338,25.347 29.841,24.85 29.254,24.85 29.254,24.144 29.25,24.14
  TOP w0.25: R1.2@17.1,92.7 17.107,92.707 17.115,92.7 23.175,92.7 ; U7.1@17.725,22.5 17.725,23.276 ; C43.2@17.85,24.47 17.85,23.709 17.725,23.584 17.725,23.276 ; U7.15@18.55,21.025 19.373,21.025 19.373,21.675 19.36,21.675 ; U7.16@18.55,21.675 19.36,21.675 ; v1(21.062,23.467) 21.481,23.467 22.548,22.4 23.2,22.4 C49.1@23.2,21.7 23.743,21.7 24.123,21.321 24.123,20.45 ; 21.265,70.882 22.25,70.882 R18.2@22.25,70.85 ; C50.2@23.2,20.45 24.123,20.45 ; 23.49,74.826 23.514,74.85 24.504,74.85 25.24,74.85 25.431,75.041 25.431,75.537 25.744,75.85 U2.9@26.9,75.85 ; 24.301,19.314 24.301,19.657 24.123,19.835 24.123,20.45 ; 24.453,69.365 25.99,69.365 26.75,70.125 R20.1@26.75,70.85 ; v1@25.769,81.8 C7.2@26.6,81.8 26.6,80.896 26.815,80.68 27.73,80.68 27.945,80.465 ; U2.1@26.9,79.85 27.699,79.85 27.958,80.109 27.958,80.452 27.945,80.465 ; R64.2@27.25,3.3 v1(27.25,6.957) ; U2.48@28.55,81.5 28.55,80.701 28.314,80.465 27.945,80.465 ; C40.2@30.2,34.1 C40.2@30.35,34.1 ; v1@30.338,25.347 v1@30.371,25.347 ; C42.2@30.63,29.2 C42.2@30.62,29.21 31.267,29.21 v1(33.045,30.988) 33.206,31.148 U5.2@33.206,31.901 U5.3@33.706,31.901 ; v1(31.476,35.532) 31.476,35.6 C37.2@30.35,35.6 C40.2@30.35,34.1 ; v1(31.984,83.792) 32,83.808 R7.2@32,84.7 ; U5.9@33.206,33.426 U5.10@32.706,33.426 32.032,34.1 C40.2@30.35,34.1 ; C8.2@35.6,81.3 C8.2@35.7,81.3 ; U2.36@35.7,79.85 C8.2@35.7,81.3 ; v1@36.556,81.384 36.472,81.3 C8.2@35.7,81.3 ; 40.836,26.835 40.901,26.9 42.838,26.9 42.843,26.896 v1(43.033,26.896) ; 41.5,80.312 R13.2@41.5,81.35 ; R62.2@44.5,7.1 44.5,6.633 47,4.133 R65.2@47,3.3 ; R49.1@46,22.3 47.091,22.3 v1(47.091,22.311) ; R65.2@47.034,3.3 47.116,3.382 47.398,3.1 50.6,3.1 ; U10.1@47.233,8.831 46.193,9.871 46.193,10.737 46.632,11.176 48.018,11.176 48.6,11.758 C65.2@48.6,12.45 49.485,11.565 49.485,10.068 50.253,9.3 C66.2@50.75,9.3 v1@51.768,9.3 ; 52.418,82.657 D3.2@53.2,82.657 ; 17.725,23.276 18.687,23.276 19.36,22.603 19.36,21.675
  TOP w0.508: 20.427,71.092 20.427,69.962 21.227,69.162 24.25,69.162 24.453,69.365 ; C10.2@24.453,74.848 24.476,74.826 24.481,74.82 C10.2@24.481,74.848
  TOP w0.6: v1(23.49,75.9) 23.49,74.826 23.49,73.81 24.453,72.847 24.453,69.365 ; C10.2@24.453,74.848 24.481,74.848 24.502,74.848 C10.2@24.504,74.85 ; v1@36.556,81.384 v1(36.556,81.506)
  TOP w0.635: v1(13.061,68.679) 13.061,68.844 14.56,68.844 16.808,71.092 20.427,71.092 21.056,71.092 21.265,70.882
  TOP w0.762: v1@12.375,63.294 12.934,62.735 12.934,56.817 v1@13.874,55.877 ; C55.2@17.516,16.332 17.602,16.418 v1(17.602,17.247) ; C43.2@17.85,24.5 20.029,24.5 v1(21.062,23.467) ; v1@30.371,25.347 30.917,25.893 v1@33.381,25.893 ; v1(33.381,25.88) v1@33.381,25.893 ; 34.35,72.7 C12.1@36,72.7 36.092,72.608 43.168,72.608 43.287,72.489 ; v1(40.196,81.45) 40.196,80.736 40.62,80.312 41.5,80.312 43.287,80.312 ; 40.836,26.835 39.962,26.835 39.02,25.893 v1@33.381,25.893 ; R65.2@47,3.3 R65.2@47.034,3.3 ; v1@47.021,25.15 47.021,25.677 52.406,25.677 53.879,27.15 53.879,38.885 54.31,39.316 54.31,57.059 55.351,58.1 ; 50.6,3.1 v1(51.4,3.1) ; 52.418,82.657 45.403,82.657 43.49,80.744 43.49,80.312 43.287,80.312 ; P2.6@59.67,58.1 P2.5@57.13,58.1 55.75,58.1 55.351,58.1 ; 43.287,72.489 44.76,71.016 54.387,71.016 55.25,70.152 55.25,58.1 55.351,58.1 ; 43.287,72.489 43.287,80.312
  Bottom w0.165: 17.595,18.285 17.595,18.832
  Bottom w0.25: C68.2@16.51,19.177 17.25,19.177 17.595,18.832 ; v1@18.979,24.47 v1(19.03,24.47)
  Bottom w0.635: v1(12.172,63.472) 12.172,67.79 v1(13.061,68.679) ; v1(43.033,26.896) 46.088,26.896 47.021,25.963 47.021,25.677
  Bottom w0.762: v1@13.95,55.733 17.217,55.733 JP2.1@17.25,55.7 ; v1@17.6,17.249 17.6,14.633 25.238,6.995 v1@27.25,6.995 ; v1(17.602,17.247) 17.602,18.293 18.382,19.073 18.382,20.542 18.979,21.139 v1@18.979,24.47 ; v1@21.16,23.369 21.583,22.946 22.891,22.946 24.161,24.216 29.208,24.216 30.168,25.177 30.168,25.232 30.333,25.397 v1(30.333,25.372) ; v1@23.49,76.02 23.49,81.76 ; v1@23.49,92.809 23.49,81.76 ; v1(31.476,35.532) 31.667,35.532 33.02,34.178 33.02,26.341 v1@33.381,25.98 ; 31.984,81.67 v1@31.984,83.68 ; 39.096,81.5 v1(36.556,81.506) 36.466,81.506 33.39,81.5 31.228,81.5 30.968,81.76 v1(25.761,81.76) 23.49,81.76 ; 39.172,81.45 39.172,80.1 SB2.2@39.197,80.1 ; 39.172,81.5 v1@40.196,81.5 ; 47.021,25.677 v1(47.021,25.067) 47.021,22.41 v1@47.084,22.346 ; 47.551,22.346 49.637,20.26 49.637,12.994 51.8,10.83 v1(51.8,9.3) 51.8,3.5 v1(51.4,3.1)
  other v1: 13.95,55.852 23.475,92.809
5V: C1.2 C2.2 C16.2 C17.2 D1.2 P2.3 P2.4 U1.1 U1.3 U3.1 U3.3 U6.5 | length 164.3
  TOP w0.25: U3.1@15.75,65.95 16.695,65.95 16.757,66.012 ; U3.3@15.75,67.85 16.652,67.85 16.668,67.866 ; U6.5@40.3,23.775 40.3,22.807 40.389,22.718 42.563,22.718 43.033,23.188 v1(43.033,23.213) ; D1.2@41.6,89.643 42.309,89.643 ; U1.3@47.649,88.071 47.649,88.974 47.687,88.974 ; U1.1@49.549,88.071 49.549,88.91 49.498,88.961 49.549,89.012
  TOP w0.5: 16.668,67.866 16.808,67.866 16.808,66.428 ; 16.757,66.012 16.808,66.063 16.808,66.428 ; 21.062,66.736 20.876,66.55 C17.2@19.3,66.55 19.284,66.55 19.162,66.428 16.808,66.428
  TOP w0.635: 42.309,89.643 42.394,89.558 43.8,89.558 ; C1.2@43.8,88.35 43.8,89.558 ; C2.2@46,88.05 46,89.558 ; 47.687,88.974 47.687,89.436 47.808,89.558 ; 49.549,89.012 49.549,89.558 ; 54.914,89.355 53.962,90.307 49.549,90.307 49.549,89.558 ; 43.8,89.558 46,89.558 ; 46,89.558 47.808,89.558 ; 47.808,89.558 49.549,89.558
  TOP w0.7: 54.914,89.355 55.225,89.044 55.225,82.392 60.902,76.715 60.902,65.742 61.956,64.688 61.956,61.66 60.936,60.64 P2.4@59.67,60.64 P2.3@57.13,60.64
  TOP w0.762: 21.062,66.736 21.202,66.876 22.738,66.876 23.818,65.796 25.177,65.796 27.679,68.298 28.847,68.298 30.066,69.517 33.165,69.517 34.295,68.387 37.204,68.387 38.728,69.911 53.18,69.911 54.031,69.06 v1(54.031,61.643) v1(54.031,60.729) 54.031,58.987 53.879,58.835 53.879,58.748 52.964,57.833 52.964,39.482 52.736,39.253 52.736,27.81 51.669,26.744 45.649,26.744 45.344,26.439 v1(45.344,25.829) 45.35,25.824 v1@45.35,25.15
  Bottom w0.635: v1(54.031,61.643) v1(54.031,60.729) 54.12,60.64 P2.3@57.13,60.64
  Bottom w0.762: v1@43.14,23.213 44.557,23.213 45.344,24 v1(45.344,25.067) v1@45.344,25.75
AIN_1: R2.2 R19.2 R20.2 U2.10 | length 33.3
  TOP w0.165: R2.2@10.5,86.1 v1(11.283,86.1) ; R19.2@25.5,72.05 R20.2@26.75,72.05 26.75,72.619 v1(27.298,73.167) 28.123,73.993 28.123,75.118 27.891,75.35 U2.10@26.9,75.35
  Bottom w0.165: v1(11.283,86.1) 11.388,86.1 14.039,83.449 14.039,75.423 15.969,73.492 18.903,73.492 19.513,72.883 26.46,72.883 26.744,73.167 v1(27.298,73.167)
BOOT0: P2.21 R28.2 R29.2 U4.94 | length 26.2
  TOP w0.165: U4.94@40.614,51.462 43.432,51.462 44.794,50.1 R28.2@45.4,50.1 R29.2@46.8,50.1 46.8,49.418 46.97,49.248 v1(47.351,49.248)
  Bottom w0.165: v1(47.351,49.248) 48.604,49.248 48.992,49.666 50.391,49.666 52.553,47.504 52.828,47.229 52.828,44.43 54.389,42.869 54.389,40.178 56.787,37.78 P2.21@57.13,37.78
